Omron CX-Programmer project 新工程 (CX-Programmer 5.00)

# PLC 新PLC1: CJ1M CPU13

## Global symbols (name address type ; comment)
AA 功能块1

## Program 新程序1 (cyclic task 0)

### Section 段1

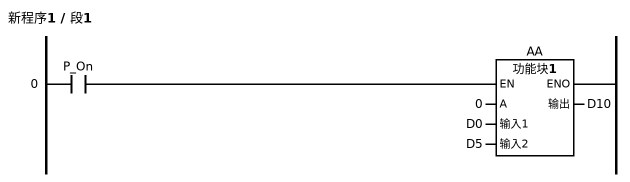
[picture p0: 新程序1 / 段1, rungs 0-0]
; rung 0
LD P_On
CALL AA : 功能块1 (A := 0, 输入1 := D0, 输入2 := D5, 输出 => D10)

### Section END
; rung 0
END(001)

## Function block 功能块1
VAR_INPUT
  A : INT;
  输入1 : REAL;
  输入2 : REAL;
END_VAR
VAR_OUTPUT
  输出 : REAL;
END_VAR
case A of
1:输出:=输入1+输入2;
2:输出:=输入1-输入2;
3:输出:=输入1*输入2;
4:
  if ( 输入2<>0.0) then
     输出:=输入1/输入2;
else
    输出:=0.0;
end_if;
else
     输出:=0.0;
end_case;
